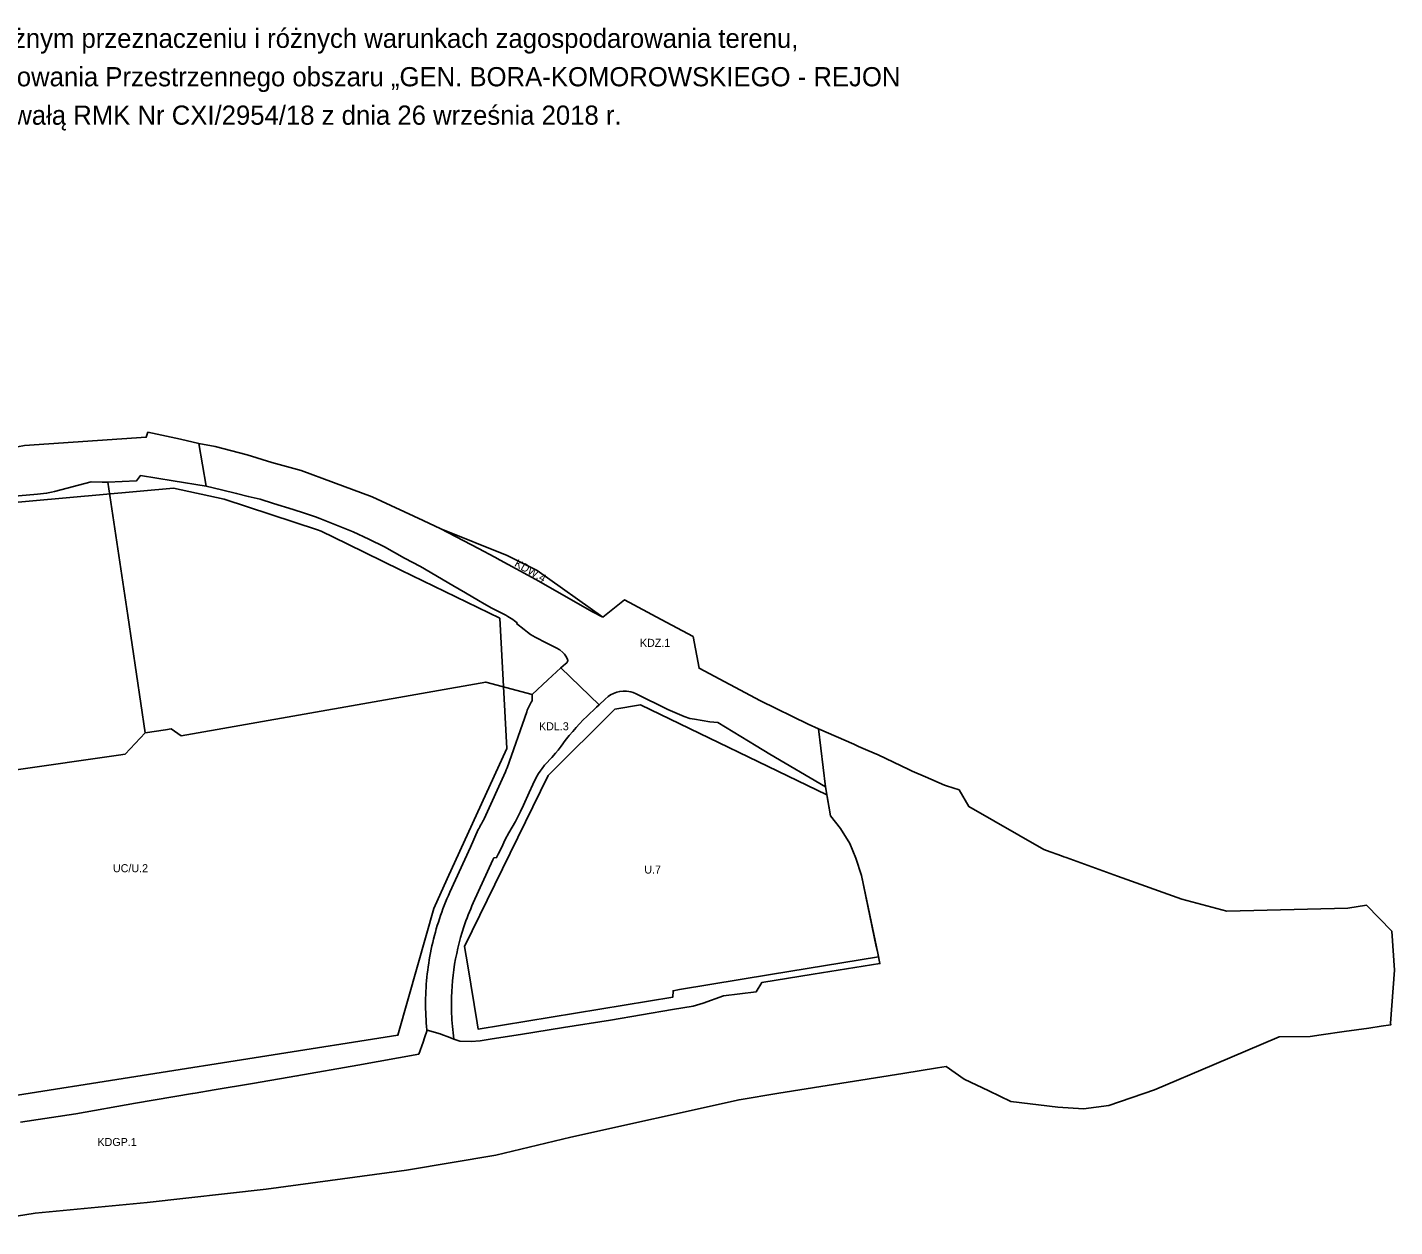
# Model space of a CAD drawing. Extents: x 7426373 to 7428079, y 5550400 to 5551210.
# Drawn here: x 7427225 to 7428079, y 5550460 to 5551210 of the extents above; entities that cross this region are included whole.
import ezdxf

# ---------------------------------------------------------------- set-up
doc = ezdxf.new("R2010")
doc.units = 0
for name, color, linetype in [('info', 7, 'Continuous'), ('linia regulacyjna wysokości zabudowy', 7, 'Continuous'), ('linie rozgraniczające', 7, 'Continuous'), ('nieprzekraczalne linie zabudowy', 7, 'Continuous'), ('przeznaczenia terenów', 7, 'Continuous')]:
    doc.layers.add(name, color=color, linetype=linetype)

msp = doc.modelspace()

# ---------------------------------------------------------------- linework, layer by layer
at = {"layer": 'linia regulacyjna wysokości zabudowy'}
msp.add_lwpolyline([(7427298.2, 5550768.96), (7427298.27, 5550769.03), (7427311.05, 5550770.9), (7427314.6, 5550771.39), (7427320.84, 5550767.11), (7427511.06, 5550800.66), (7427540.08, 5550792.88)], dxfattribs=at)
at = {"layer": 'linie rozgraniczające'}
for p, q in [((7427320.39, 5550952.48), (7427299.9, 5550956.76)), ((7427331.81, 5550949.61), (7427336.38, 5550923.03)), ((7427490.56, 5550861), (7427470.26, 5550872.89)), ((7427540.08, 5550792.88), (7427539.97, 5550788.93)), ((7427723.19, 5550735.17), (7427718.82, 5550771.46))]:
    msp.add_line(p, q, dxfattribs=at)
for points in [[(7427299.9, 5550956.76), (7427299.03, 5550953.57), (7427222.94, 5550948.43), (7427200.83, 5550944.38)], [(7427361.96, 5550942.53), (7427341.93, 5550947.82), (7427331.81, 5550949.61), (7427320.39, 5550952.48)], [(7427440, 5550916.48), (7427416.04, 5550925.39), (7427395.72, 5550932.79), (7427377.5, 5550937.88), (7427361.96, 5550942.53)], [(7427470.26, 5550872.89), (7427460.34, 5550878.07), (7427454.07, 5550881.57), (7427447.8, 5550885.07), (7427437.98, 5550889.85), (7427428.15, 5550894.63), (7427417.78, 5550898.76), (7427407.4, 5550902.9), (7427404.64, 5550903.8), (7427397.73, 5550906.09), (7427390.81, 5550908.38), (7427378.55, 5550912.2), (7427370.08, 5550914.84), (7427362.73, 5550916.7), (7427355.37, 5550918.55), (7427345.88, 5550920.79), (7427336.38, 5550923.03), (7427315.88, 5550926.33), (7427295.38, 5550929.62), (7427292.93, 5550926.39), (7427275.04, 5550925.65), (7427271.4, 5550925.65), (7427264.66, 5550925.66), (7427241.76, 5550919.75)], [(7427241.76, 5550919.75), (7427239.69, 5550919.3), (7427236.75, 5550918.66), (7427231.06, 5550918.04), (7427207, 5550916.03)], [(7427281.67, 5550755.01), (7427285.78, 5550755.6), (7427298.2, 5550768.96), (7427287.39, 5550842.19), (7427275.04, 5550925.65)], [(7427524.37, 5550879.68), (7427482.89, 5550896.49), (7427472.05, 5550901.55), (7427440, 5550916.48)], [(7427482.89, 5550896.49), (7427506.54, 5550884.03), (7427516.74, 5550878.63), (7427520.02, 5550876.9), (7427542.35, 5550864.69), (7427577.72, 5550844.62), (7427584.25, 5550841.2)], [(7427584.25, 5550841.2), (7427543.26, 5550870.3), (7427524.37, 5550879.68)], [(7427624.83, 5550783.52), (7427604.9, 5550793.29), (7427603.03, 5550794.09), (7427601.68, 5550794.5), (7427600.36, 5550794.79), (7427598.93, 5550794.98), (7427596.78, 5550795.02), (7427594.71, 5550794.8), (7427592.87, 5550794.37), (7427590.86, 5550793.63), (7427588.99, 5550792.67), (7427587.45, 5550791.61), (7427585.65, 5550790.02), (7427581.86, 5550786.43), (7427557.9, 5550809.6), (7427560.85, 5550812.09), (7427561.62, 5550812.76), (7427562.01, 5550813.63), (7427562.22, 5550814.15), (7427562.27, 5550814.49), (7427562.21, 5550814.8), (7427561.72, 5550815.76), (7427561.08, 5550816.82), (7427560.2, 5550818.02), (7427559.24, 5550819.09), (7427557.26, 5550820.8), (7427555.1, 5550822.11), (7427549.17, 5550825.07), (7427541.99, 5550828.69), (7427539.02, 5550830.46), (7427537.04, 5550831.84), (7427534.94, 5550833.48), (7427530.33, 5550837.32), (7427530.65, 5550837.7), (7427529.05, 5550838.95), (7427527.86, 5550839.81), (7427526.95, 5550840.41), (7427525.85, 5550841.09), (7427524.76, 5550841.72), (7427523.5, 5550842.38), (7427514.89, 5550846.9), (7427510.08, 5550849.58), (7427506.43, 5550851.69), (7427498.49, 5550856.34), (7427490.56, 5550861)], [(7427620.54, 5550839.82), (7427597.79, 5550851.97), (7427584.25, 5550841.2)], [(7427177.53, 5550460.5), (7427229.52, 5550468.88), (7427299.49, 5550475.55), (7427373.91, 5550483.93), (7427461.48, 5550495.77), (7427517.43, 5550505.23), (7427564.1, 5550516.34), (7427669.31, 5550539.8), (7427694.15, 5550543.8), (7427771.57, 5550556.26), (7427793.15, 5550559.73), (7427798.57, 5550560.6), (7427809.96, 5550552.6), (7427825.37, 5550545.24), (7427838.94, 5550538.76), (7427868.42, 5550535.06), (7427884.46, 5550534.11), (7427900.19, 5550536.25), (7427928.72, 5550545.91), (7427966.11, 5550561.69), (7428006.69, 5550579.14), (7428026.08, 5550579.29), (7428032.86, 5550580.27), (7428047.19, 5550582.32), (7428062.66, 5550584.53), (7428070.46, 5550585.65), (7428076.34, 5550586.49), (7428076.22, 5550587.62), (7428078.79, 5550620.77), (7428077, 5550645.04), (7428061.13, 5550661.3), (7428049.59, 5550659.52), (7427974.04, 5550657.66), (7427945.91, 5550665.05), (7427905.73, 5550679.5), (7427873.55, 5550691.07), (7427872.11, 5550691.59), (7427870.59, 5550692.13), (7427861.31, 5550695.45), (7427859.6, 5550696.06), (7427812.8, 5550722.89), (7427806.73, 5550733.28), (7427798.77, 5550735.94), (7427797.61, 5550736.33), (7427785.78, 5550741.48), (7427777.49, 5550745.1), (7427775.32, 5550746.04), (7427756.11, 5550755.18), (7427749.69, 5550757.98), (7427743.97, 5550760.48), (7427740.94, 5550761.8), (7427718.82, 5550771.46), (7427712.34, 5550774.29), (7427682.75, 5550789.04), (7427644.33, 5550809.36), (7427640.54, 5550829.14), (7427620.54, 5550839.82)], [(7427540.08, 5550792.88), (7427549.77, 5550802.16), (7427557.9, 5550809.6)], [(7427501.44, 5550697.59), (7427506.4, 5550708.52), (7427506.84, 5550709.44), (7427507.3, 5550710.34), (7427507.8, 5550711.23), (7427508.32, 5550712.11), (7427508.79, 5550712.89), (7427509.24, 5550713.7), (7427509.66, 5550714.52), (7427510.06, 5550715.35), (7427523.35, 5550744.6), (7427523.87, 5550745.83), (7427524.34, 5550747.08), (7427536.64, 5550782.14)], [(7427581.86, 5550786.43), (7427580.26, 5550784.92), (7427574.17, 5550779.15), (7427571.98, 5550777), (7427569.61, 5550774.56), (7427567.51, 5550772.3), (7427565.35, 5550769.85), (7427563.14, 5550767.23), (7427560.65, 5550764.09), (7427558.12, 5550760.71), (7427556.25, 5550758.22), (7427554.6, 5550756.18), (7427552.39, 5550753.63), (7427551.3, 5550752.45), (7427549.19, 5550750.24), (7427547.81, 5550748.68), (7427546.22, 5550746.71), (7427545.04, 5550745.08), (7427543.97, 5550743.47), (7427542.52, 5550741.03), (7427540.39, 5550736.68), (7427538.09, 5550731.61), (7427534.56, 5550723.84), (7427532.78, 5550719.91), (7427531.39, 5550716.94), (7427529.67, 5550713.61), (7427527.59, 5550710.02), (7427525.38, 5550706.6), (7427523.26, 5550702.25), (7427520.78, 5550697.13), (7427518.89, 5550693.26), (7427517.83, 5550691.07), (7427516.1, 5550690.93)], [(7427539.97, 5550788.93), (7427539.47, 5550788.13), (7427538.99, 5550787.31), (7427538.53, 5550786.48), (7427538.1, 5550785.63), (7427537.7, 5550784.77), (7427537.32, 5550783.9), (7427536.96, 5550783.03), (7427536.64, 5550782.14)], [(7427624.83, 5550783.52), (7427634.89, 5550779.13), (7427638.42, 5550778.01), (7427641.38, 5550777.41)], [(7427641.38, 5550777.41), (7427651.06, 5550775.93), (7427656.05, 5550775.43)], [(7427723.19, 5550735.17), (7427688.43, 5550755.63), (7427679.92, 5550760.83), (7427656.05, 5550775.43)], [(7427281.67, 5550755.01), (7427216.25, 5550745.55), (7427148.47, 5550735.75), (7427120.11, 5550731.52), (7427078.99, 5550725.38), (7427074.95, 5550724.79)], [(7427723.19, 5550735.17), (7427726.34, 5550717.14), (7427732.64, 5550709.23), (7427738.39, 5550699.91), (7427742.27, 5550690.75), (7427745.65, 5550679.88), (7427754.98, 5550635.45), (7427755.86, 5550631.28)], [(7427488.62, 5550669.37), (7427501.44, 5550697.59)], [(7427516.1, 5550690.93), (7427515.5, 5550689.61), (7427503.26, 5550662.68)], [(7427482.1, 5550652.77), (7427482.82, 5550654.88), (7427483.57, 5550656.98), (7427484.34, 5550659.07), (7427485.14, 5550661.16), (7427485.97, 5550663.23), (7427486.83, 5550665.28), (7427487.71, 5550667.33), (7427488.62, 5550669.37)], [(7427497.38, 5550647.69), (7427498.03, 5550649.6), (7427498.7, 5550651.49), (7427499.4, 5550653.38), (7427500.12, 5550655.26), (7427500.87, 5550657.13), (7427501.65, 5550659), (7427502.44, 5550660.84), (7427503.26, 5550662.68)], [(7427474.53, 5550583.32), (7427474.23, 5550583.43), (7427474.04, 5550585.61), (7427473.87, 5550587.78), (7427473.74, 5550589.97), (7427473.63, 5550592.16), (7427473.55, 5550594.35), (7427473.49, 5550596.54), (7427473.47, 5550598.74), (7427473.47, 5550600.93), (7427473.51, 5550603.13), (7427473.57, 5550605.33), (7427473.66, 5550607.53), (7427473.78, 5550609.73), (7427473.93, 5550611.93), (7427474.11, 5550614.13), (7427474.31, 5550616.32), (7427474.55, 5550618.51), (7427474.81, 5550620.7), (7427475.1, 5550622.89), (7427475.42, 5550625.07), (7427475.77, 5550627.24), (7427476.14, 5550629.41), (7427476.55, 5550631.58), (7427476.98, 5550633.74), (7427477.44, 5550635.89), (7427477.93, 5550638.03), (7427478.45, 5550640.16), (7427478.99, 5550642.29), (7427479.56, 5550644.41), (7427480.15, 5550646.51), (7427480.78, 5550648.61), (7427481.43, 5550650.7), (7427482.1, 5550652.77)], [(7427489.68, 5550593.59), (7427489.59, 5550597.01), (7427489.57, 5550600.43), (7427489.63, 5550603.86), (7427489.77, 5550607.29), (7427489.98, 5550610.72), (7427490.28, 5550614.15), (7427490.64, 5550617.57), (7427491.09, 5550620.99), (7427491.61, 5550624.39), (7427492.21, 5550627.78), (7427492.89, 5550631.15), (7427493.64, 5550634.51), (7427494.47, 5550637.84), (7427495.37, 5550641.15), (7427496.34, 5550644.43), (7427497.38, 5550647.69)], [(7427640.61, 5550598.22), (7427646.85, 5550600.02), (7427659.51, 5550604.69), (7427680.05, 5550607.28), (7427683.49, 5550612.98), (7427715.52, 5550618.2), (7427757.22, 5550624.85), (7427755.86, 5550631.28)], [(7427491.13, 5550577.7), (7427494.86, 5550576.31), (7427501.91, 5550576.1), (7427507.52, 5550576.53), (7427514.99, 5550577.72), (7427532.68, 5550580.53), (7427559.59, 5550584.8), (7427588.87, 5550589.45), (7427627.61, 5550596.09), (7427640.61, 5550598.22)], [(7427491.13, 5550577.7), (7427490.86, 5550579.67), (7427490.61, 5550581.65), (7427490.39, 5550583.63), (7427490.2, 5550585.62), (7427490.03, 5550587.61), (7427489.89, 5550589.6), (7427489.77, 5550591.6), (7427489.68, 5550593.59)], [(7427469.3, 5550568.16), (7427472, 5550575.81), (7427472.88, 5550578.52), (7427474.53, 5550583.32)], [(7427474.53, 5550583.32), (7427482.51, 5550580.91), (7427484.06, 5550580.33), (7427487.52, 5550579.04), (7427491.13, 5550577.7)], [(7427220.33, 5550525.84), (7427254.95, 5550531.02), (7427292.26, 5550537.59), (7427327.88, 5550543.65), (7427327.88, 5550543.65), (7427329.53, 5550543.93), (7427341.36, 5550545.95), (7427365.41, 5550549.99), (7427393.05, 5550554.71), (7427431.17, 5550561.44), (7427469.3, 5550568.16)]]:
    msp.add_lwpolyline(points, dxfattribs=at)
at = {"layer": 'nieprzekraczalne linie zabudowy'}
for points in [[(7427408.31, 5550895.03), (7427406.05, 5550895.78), (7427347.6, 5550914.84), (7427315.95, 5550921.81), (7427184.04, 5550909.87), (7427054.18, 5550888.2), (7427058.04, 5550862.98), (7427058.77, 5550863.09), (7427066.5, 5550820.89)], [(7427519.89, 5550840.51), (7427457.98, 5550870.65), (7427424.47, 5550887.1), (7427408.31, 5550895.03)], [(7427524.15, 5550759.24), (7427519.89, 5550840.51)], [(7427468.63, 5550624.1), (7427478.62, 5550659.17), (7427486.97, 5550677.7), (7427524.15, 5550759.24)], [(7427046.83, 5550515.5), (7427456.13, 5550580.05), (7427468.63, 5550624.1)]]:
    msp.add_lwpolyline(points, dxfattribs=at)
msp.add_lwpolyline([(7427756.34, 5550629.05), (7427755.87, 5550631.28), (7427745.65, 5550679.88), (7427742.27, 5550690.75), (7427738.39, 5550699.91), (7427732.64, 5550709.23), (7427726.34, 5550717.14), (7427724.05, 5550730.24), (7427607.69, 5550786.42), (7427591.6, 5550783.71), (7427549.99, 5550742.27), (7427497.81, 5550635.4), (7427499.79, 5550623.38), (7427505.64, 5550587.86), (7427506.29, 5550583.93), (7427627.87, 5550603.8), (7427628.08, 5550607.89), (7427632.11, 5550608.55), (7427688.94, 5550617.93)], close=True, dxfattribs=at)

# ---------------------------------------------------------------- texts
at = {"layer": 'info'}
for s, p in [('Materiał pomocniczy zawierający linie rozgraniczające teren o różnym przeznaczeniu i różnych warunkach zagospodarowania terenu, ', (7426758.2, 5551196.82)), ('opracowane w skali 1:1000 pochodzące z Miejscowego Planu Zagospodarowania Przestrzennego obszaru „GEN. BORA-KOMOROWSKIEGO - REJON ', (7426688.24, 5551172.82)), ('KONCENTRACJI USŁUG” zatwierdzonego uchwałą RMK Nr CXI/2954/18 z dnia 26 września 2018 r.', (7426878.83, 5551148.82))]:
    msp.add_text(s, height=12, dxfattribs=at).set_placement(p)
at = {"layer": 'przeznaczenia terenów'}
msp.add_text('KDW.4', height=5, rotation=330.07701, dxfattribs=at).set_placement((7427528.55, 5550873.35))
for s, p in [('KDZ.1', (7427607.34, 5550822.69)), ('KDL.3', (7427544.3, 5550770.57)), ('UC/U.2', (7427278.18, 5550681.91)), ('U.7', (7427610.08, 5550681.06)), ('KDGP.1', (7427268.51, 5550510.89))]:
    msp.add_text(s, height=5, dxfattribs=at).set_placement(p)

doc.saveas('drawing.dxf')
